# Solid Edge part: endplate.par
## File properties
Author: Robert a Rhodes jr
Template: NORMENG.PAR
Last saved by: Robert a Rhodes jr
Revision: 1
Application: Solid Edge
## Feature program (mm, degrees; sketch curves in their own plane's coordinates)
sketch for "unnamed Protrusion 1" plane through (0, 0, 0) normal (0, 0, 1) x-axis (1, 0, 0)
  line (-50.8, 46.0858) -> (-50.8, -55.5142)
  line (-50.8, -55.5142) -> (50.8, -55.5142)
  line (50.8, -55.5142) -> (50.8, 46.0858)
  line (50.8, 46.0858) -> (-50.8, 46.0858)
extrude "unnamed Protrusion 1" add finite 12.7 along +normal
sketch for "unnamed Hole 1" plane through (0, -4.7142, 12.7) normal (0, 0, 1) x-axis (1, 0, 0)
  hole centre (-38.1, -38.1) bore radius 3.175
hole "unnamed Hole 1" through
sketch for "unnamed Hole 2" plane through (0, -4.7142, 12.7) normal (0, 0, 1) x-axis (1, 0, 0)
  hole centre (38.1, -38.1) bore radius 3.175
hole "unnamed Hole 2" through
sketch for "unnamed Hole 3" plane through (0, -4.7142, 12.7) normal (0, 0, 1) x-axis (1, 0, 0)
  hole centre (38.1, 38.1) bore radius 3.175
hole "unnamed Hole 3" through
sketch for "unnamed Hole 4" plane through (0, -4.7142, 12.7) normal (0, 0, 1) x-axis (1, 0, 0)
  hole centre (-38.1, 38.1) bore radius 3.175
  dimension (linear) = 38.1
hole "unnamed Hole 4" through
pattern "unnamed Pattern 1" of "unnamed Hole 1", "unnamed Hole 2", "unnamed Hole 3", "unnamed Hole 4"
sketch for "unnamed Hole 5" plane through (0, -4.7142, 12.7) normal (0, 0, 1) x-axis (1, 0, 0)
  hole centre (0, 0) bore radius 12.7
hole "unnamed Hole 5" through
sketch for "unnamed Hole 6" plane through (0, -4.7142, 12.7) normal (0, 0, 1) x-axis (1, 0, 0)
  hole centre (-20.6375, 0) bore radius 2.3812
  dimension (linear) = 20.6375
hole "unnamed Hole 6" through
pattern "unnamed Pattern 2" of "unnamed Hole 6"
pattern "unnamed Pattern 3"
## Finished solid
Body 1: solid body, 15 faces, 30 edges, 8 vertices.
  Faces by surface: cylinder 9, plane 6
  Edges by curve: circle 18, line 12
Bounding box of the edges (mm): 101.600 x 101.600 x 12.700, from (-50.8, -55.5142, 0) to (50.8, 46.0858, 12.7).
Cylindrical faces by radius (mm): R2.3812 x4, R3.175 x4, R12.7 x1
Planar faces by outward normal: +x 1, +y 1, +z 1, -x 1, -y 1, -z 1
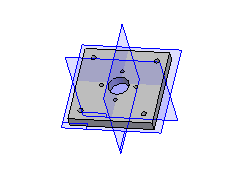
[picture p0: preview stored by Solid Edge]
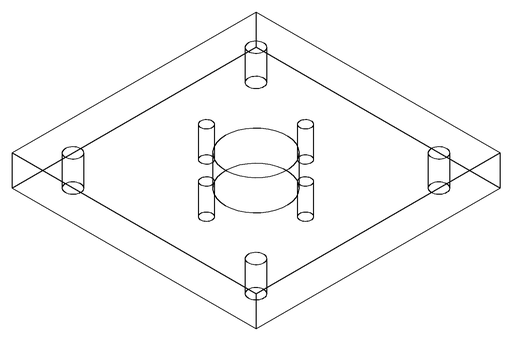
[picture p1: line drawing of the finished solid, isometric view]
